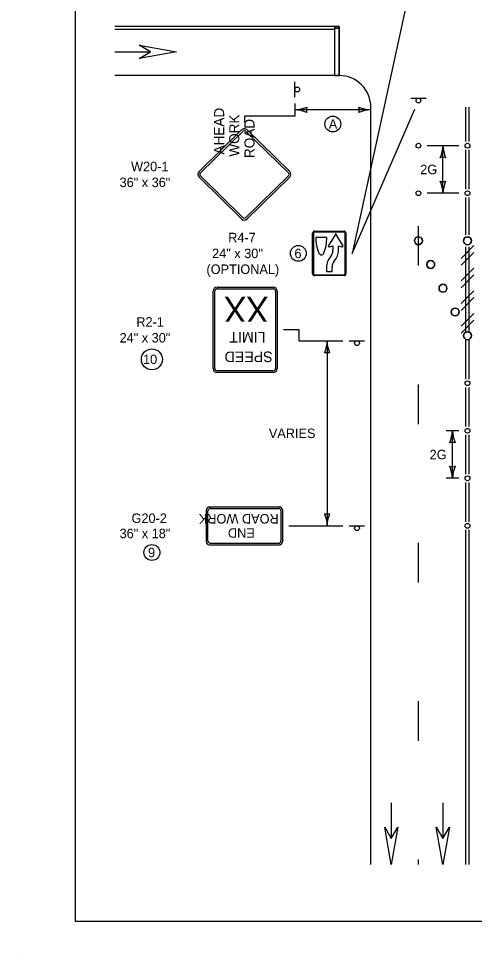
# Model space of a CAD drawing. Extents: x 49991.4 to 50021, y 49987.6 to 50011.4.
# Drawn here: x 49999.02 to 50001.9, y 49987.6 to 49993.5 of the extents above; entities that cross this region are included whole.
import ezdxf

# ---------------------------------------------------------------- set-up
doc = ezdxf.new("R2010")
doc.units = 0
for name, color, linetype in [('Level 1', 7, 'Continuous'), ('Level 2', 7, 'Continuous'), ('Level 25', 7, 'Continuous'), ('Level 3', 7, 'Continuous')]:
    doc.layers.add(name, color=color, linetype=linetype)

# ---------------------------------------------------------------- blocks, each defined once
blk = doc.blocks.new('R4.7')
at = {"layer": 'Level 25'}
for p, q in [((-42.9, -53.4), (-42.9, 48.9)), ((-40.7, 48.9), (-40.7, -53.4)), ((-37.6, 54.2), (36.5, 54.2)), ((36.5, 52), (-37.6, 52)), ((15.6, 47.6), (-3, 18.2)), ((34.1, 18.2), (15.6, 47.6)), ((39.5, -53.4), (39.5, 48.9)), ((41.7, 48.9), (41.7, -53.4)), ((-6.8, 38.4), (-35, 38.4)), ((0.3, 14.1), (8.5, 16.7)), ((8.5, 16.7), (8.5, 5.4)), ((22.6, 5.4), (22.6, 16.7)), ((22.6, 16.7), (30.9, 14.1)), ((-7.6, -36.9), (-7.6, -48.1)), ((6.5, -48.1), (6.5, -36.9)), ((-37.6, -56.5), (36.5, -56.5)), ((36.5, -58.7), (-37.6, -58.7)), ((-7.6, -48.1), (6.5, -48.1))]:
    blk.add_line(p, q, dxfattribs=at)
blk.add_lwpolyline([(15.8, 47.3), (15.5, 47.6)], dxfattribs=at)
for centre, radius, start, end in [((-37.6, 48.9), 5.29, 90, 180), ((-37.6, 48.9), 3.09, 90, 180), ((36.5, 48.9), 5.29, 0, 90), ((36.5, 48.9), 3.09, 0, 90), ((70.9, 38), 105.8, 179.7952, 201.7879), ((-112.6, 38), 105.8, 338.2124, 0.205), ((-0.6, 16.8), 2.79, 147.757, 287.6186), ((-16.2, 5.4), 24.7, 318.1901, 0), ((-16.2, 5.4), 38.8, 318.1901, 0), ((31.8, 16.8), 2.79, 252.3804, 32.2438), ((-20.9, 1.3), 7.06, 201.7877, 338.2132), ((31.2, -36.9), 38.8, 138.1903, 180), ((31.2, -36.9), 24.7, 138.1903, 180), ((-37.6, -53.4), 5.29, 180, 270), ((-37.6, -53.4), 3.09, 180, 270), ((36.5, -53.4), 3.09, 270, 0), ((36.5, -53.4), 5.29, 270, 0)]:
    blk.add_arc(centre, radius, start, end, dxfattribs=at)
blk = doc.blocks.new('ARR')
at = {"layer": 'Level 3'}
for centre, radius, start, end in [((1.53, 37.02), 37.05, 247.45601, 267.63952), ((-21.37, 0), 9.13, 342.13882, 17.86118), ((1.92, -38.79), 38.83, 92.82731, 112.07716)]:
    blk.add_arc(centre, radius, start, end, dxfattribs=at)
blk = doc.blocks.new('G20-2')
at = {"layer": 'Level 1'}
for p, q in [((0.2197, 0.1196), (-0.2203, 0.1196)), ((-0.2403, -0.1004), (-0.2403, 0.0996)), ((-0.2303, -0.0954), (-0.2303, 0.0946)), ((0.2147, 0.1096), (-0.2153, 0.1096)), ((0.2297, 0.0946), (0.2297, -0.0954)), ((0.2397, 0.0996), (0.2397, -0.1004)), ((0.2147, -0.1104), (-0.2153, -0.1104)), ((0.2196, -0.1204), (-0.2204, -0.1204))]:
    blk.add_line(p, q, dxfattribs=at)
for centre, radius, start, end in [((-0.2203, 0.0996), 0.02, 90, 180), ((0.2197, 0.0996), 0.02, 360, 90), ((-0.2153, 0.0946), 0.015, 90, 180), ((0.2147, 0.0946), 0.015, 360, 90), ((-0.2204, -0.1004), 0.02, 180, 270), ((-0.2153, -0.0954), 0.015, 180, 270), ((0.2147, -0.0954), 0.015, 270, 360), ((0.2196, -0.1004), 0.02, 270, 360)]:
    blk.add_arc(centre, radius, start, end, dxfattribs=at)
for s, p in [('END', (-0.0655, 0.015)), ('ROAD WORK', (-0.2162, -0.075))]:
    blk.add_text(s, height=0.06, rotation=360, dxfattribs=at).set_placement(p)

msp = doc.modelspace()

# ---------------------------------------------------------------- linework, layer by layer
at = {"layer": 'Level 1'}
for p, q in [((50001.0473, 49993.4505), (49999.6305, 49993.4505)), ((50001.0173, 49993.4305), (49999.6305, 49993.4305)), ((50001.0173, 49993.4505), (50001.0173, 49993.1404)), ((50001.0173, 49993.4405), (50001.0473, 49993.4405)), ((50001.0473, 49993.4505), (50001.0473, 49993.1404)), ((49999.6305, 49993.2905), (49999.8564, 49993.2905)), ((49999.6305, 49993.2901), (49999.8564, 49993.2901)), ((50001.0473, 49993.1404), (49999.6305, 49993.1404)), ((50000.7673, 49993.0044), (50000.7673, 49993.1004)), ((50001.4994, 49992.9977), (50001.5954, 49992.9977)), ((50001.2473, 49988.1586), (50001.2473, 49992.9404)), ((50001.8473, 49992.7239), (50001.8473, 49992.9404)), ((50001.8673, 49992.7239), (50001.8673, 49992.9404)), ((50000.163, 49992.5343), (50000.4313, 49992.7971)), ((50000.1716, 49992.5255), (50000.4399, 49992.7883)), ((50000.4586, 49992.7883), (50000.7268, 49992.5255)), ((50000.4672, 49992.7971), (50000.7354, 49992.5343)), ((50001.8473, 49992.4239), (50001.8473, 49992.6715)), ((50001.8673, 49992.4239), (50001.8673, 49992.6715)), ((50000.4313, 49992.2355), (50000.163, 49992.4983)), ((50000.4399, 49992.2443), (50000.1716, 49992.5071)), ((50000.7268, 49992.5071), (50000.4586, 49992.2443)), ((50000.7354, 49992.4983), (50000.4672, 49992.2355)), ((50001.8473, 49992.1356), (50001.8473, 49992.3715)), ((50001.8673, 49992.1356), (50001.8673, 49992.3715)), ((50001.5474, 49991.9404), (50001.5474, 49992.1904)), ((50001.5225, 49992.0977), (50001.5225, 49992.0977)), ((50001.8169, 49991.9865), (50001.8977, 49992.0673)), ((50001.8323, 49992.0977), (50001.8323, 49992.0977)), ((50001.8473, 49991.5239), (50001.8473, 49992.0598)), ((50001.8673, 49991.5239), (50001.8673, 49992.0598)), ((50001.8169, 49991.9436), (50001.8977, 49992.0244)), ((50001.5999, 49991.9477), (50001.5999, 49991.9477)), ((50001.8169, 49991.8436), (50001.8977, 49991.9244)), ((50001.8169, 49991.8008), (50001.8977, 49991.8816)), ((50000.2769, 49991.805), (50000.6313, 49991.805)), ((50000.2516, 49991.2902), (50000.2516, 49991.7797)), ((50000.2621, 49991.2902), (50000.2621, 49991.7797)), ((50000.2769, 49991.7944), (50000.6313, 49991.7944)), ((50000.6461, 49991.7797), (50000.6461, 49991.2902)), ((50000.6567, 49991.7797), (50000.6567, 49991.2902)), ((50001.6774, 49991.7977), (50001.6774, 49991.7977)), ((50001.8169, 49991.7008), (50001.8977, 49991.7816)), ((50001.8169, 49991.6579), (50001.8977, 49991.7387)), ((50001.7549, 49991.6477), (50001.7549, 49991.6477)), ((50001.8169, 49991.5579), (50001.8977, 49991.6387)), ((50001.8169, 49991.5151), (50001.8977, 49991.5959)), ((50001.1113, 49991.4657), (50001.2073, 49991.4657)), ((50001.8323, 49991.4977), (50001.8323, 49991.4977)), ((50001.8473, 49991.2239), (50001.8473, 49991.4748)), ((50001.8673, 49991.2239), (50001.8673, 49991.4715)), ((50000.6313, 49991.2755), (50000.2769, 49991.2755)), ((50000.6313, 49991.2649), (50000.2769, 49991.2649)), ((50000.4541, 49991.2649), (50000.4541, 49991.2649)), ((50001.5474, 49990.9404), (50001.5474, 49991.1904)), ((50001.8473, 49990.9239), (50001.8473, 49991.1715)), ((50001.8673, 49990.9239), (50001.8673, 49991.1715)), ((50001.8473, 49990.6239), (50001.8473, 49990.8715)), ((50001.8673, 49990.6239), (50001.8673, 49990.8715)), ((50001.8473, 49990.3239), (50001.8473, 49990.5715)), ((50001.8673, 49990.3239), (50001.8673, 49990.5715)), ((50001.1113, 49990.2977), (50001.2073, 49990.2977)), ((50001.8473, 49988.1586), (50001.8473, 49990.2715)), ((50001.8673, 49988.1586), (50001.8673, 49990.2715)), ((50001.5474, 49989.9404), (50001.5474, 49990.1904)), ((50001.5474, 49988.9404), (50001.5474, 49989.1904)), ((50001.376, 49988.5487), (50001.376, 49988.3228)), ((50001.3764, 49988.5487), (50001.3764, 49988.3228)), ((50001.7008, 49988.5487), (50001.7008, 49988.3228)), ((50001.7012, 49988.5487), (50001.7012, 49988.3228)), ((50001.5474, 49988.1586), (50001.5474, 49988.1904)), ((49999.0245, 49987.5988), (49999.0245, 49987.5988))]:
    msp.add_line(p, q, dxfattribs=at)
for points in [[(49999.3835, 49998.9992), (50016.7501, 49998.9992), (50016.7501, 49987.7988), (49999.3835, 49987.7988)], [(49999.7841, 49993.3321), (50000.0206, 49993.2905), (49999.7841, 49993.2485), (49999.8563, 49993.2905)], [(50001.418, 49988.3951), (50001.3764, 49988.1586), (50001.3344, 49988.3951), (50001.3764, 49988.3229)], [(50001.7428, 49988.3951), (50001.7012, 49988.1586), (50001.6592, 49988.3951), (50001.7012, 49988.3229)]]:
    msp.add_lwpolyline(points, close=True, dxfattribs=at)
for points in [[(50001.0473, 49993.4405), (50001.0473, 49993.4505), (50001.0173, 49993.4505), (50001.0173, 49993.4405), (50001.0473, 49993.4405)], [(50001.0173, 49993.1404), (50001.0473, 49993.1404), (50001.0473, 49993.4405), (50001.0173, 49993.4405), (50001.0173, 49993.1404)]]:
    msp.add_lwpolyline(points, dxfattribs=at)
for centre, radius in [((50000.7825, 49993.0525), 0.0152), ((50001.5475, 49992.9825), 0.0152), ((50001.5474, 49992.6977), 0.015), ((50001.8573, 49992.6977), 0.015), ((50001.5474, 49992.3977), 0.015), ((50001.8573, 49992.3977), 0.015), ((50001.5474, 49992.0977), 0.025), ((50001.8573, 49992.0977), 0.025), ((50001.6249, 49991.9477), 0.025), ((50001.7024, 49991.7977), 0.025), ((50001.7798, 49991.6477), 0.025), ((50001.8573, 49991.4977), 0.025), ((50001.1594, 49991.4506), 0.0152), ((50001.8573, 49991.1977), 0.015), ((50001.8573, 49990.8977), 0.015), ((50001.8573, 49990.5977), 0.015), ((50001.1594, 49990.2825), 0.0152), ((50001.8573, 49990.2977), 0.015)]:
    msp.add_circle(centre, radius, dxfattribs=at)
for centre, radius, start, end in [((50001.0473, 49992.9404), 0.2, 359.99985, 90), ((50001.5474, 49992.0977), 0.025, 0, 180), ((50001.8573, 49992.0977), 0.025, 0, 180), ((50001.5474, 49992.0977), 0.025, 180, 0), ((50001.8573, 49992.0977), 0.025, 180, 0), ((50001.6249, 49991.9477), 0.025, 0, 180), ((50001.6249, 49991.9477), 0.025, 180, 0), ((50000.2769, 49991.7797), 0.0253, 90, 180), ((50000.6313, 49991.7797), 0.0253, 360, 90), ((50001.7024, 49991.7977), 0.025, 0, 180), ((50000.2769, 49991.7797), 0.0148, 90, 180), ((50000.6313, 49991.7797), 0.0148, 360, 90), ((50001.7024, 49991.7977), 0.025, 180, 0), ((50001.7798, 49991.6477), 0.025, 0, 180), ((50001.7798, 49991.6477), 0.025, 180, 0), ((50001.8573, 49991.4977), 0.025, 0, 180), ((50001.8573, 49991.4977), 0.025, 180, 0), ((50000.2769, 49991.2902), 0.0253, 180, 270), ((50000.2769, 49991.2902), 0.0148, 180, 270), ((50000.6313, 49991.2902), 0.0148, 270, 360), ((50000.6313, 49991.2902), 0.0253, 270, 360)]:
    msp.add_arc(centre, radius, start, end, dxfattribs=at)
for centre, major_axis, ratio, start_param, end_param in [((50000.4492, 49992.7792), (0.0255, 0), 0.98963, 0.785394, 2.356194), ((50000.4492, 49992.7792), (0.0132, 0), 0.98, 0.785394, 2.356194), ((50000.181, 49992.5163), (-0.0255, 0), 0.98963, 5.497795, 7.068583), ((50000.181, 49992.5163), (-0.0132, 0), 0.98, 5.497795, 7.068583), ((50000.7174, 49992.5163), (0.0132, 0), 0.98, 5.497787, 7.068583), ((50000.7174, 49992.5163), (0.0255, 0), 0.98963, 5.497787, 7.068583), ((50000.4492, 49992.2535), (0.0255, 0), 0.98963, 3.926991, 5.497787), ((50000.4492, 49992.2535), (0.0132, 0), 0.98, 3.926991, 5.497787)]:
    msp.add_ellipse(centre, major_axis=major_axis, ratio=ratio, start_param=start_param, end_param=end_param, dxfattribs=at)
at = {"layer": 'Level 2'}
for centre, radius in [((50001.0073, 49992.8343), 0.0501), ((50000.7894, 49992.0177), 0.0501), ((49999.8653, 49991.3488), 0.0662), ((49999.8653, 49990.1296), 0.0501)]:
    msp.add_circle(centre, radius, dxfattribs=at)
at = {"layer": 'Level 3'}
for p, q in [((50001.5475, 49993.945), (50001.1302, 49992.0177)), ((50000.7673, 49992.9644), (50000.7673, 49992.8844)), ((50001.2473, 49992.9244), (50000.7673, 49992.9244)), ((50001.1302, 49992.0177), (50001.5249, 49992.9273)), ((50000.4492, 49992.8844), (50000.4492, 49992.8444)), ((50000.7673, 49992.8844), (50000.4492, 49992.8844)), ((50001.8023, 49992.6977), (50001.6024, 49992.6977)), ((50001.7024, 49992.3977), (50001.7024, 49992.6977)), ((50001.8023, 49992.3977), (50001.6024, 49992.3977)), ((50000.7943, 49991.4657), (50001.0713, 49991.4657)), ((50000.9713, 49991.4657), (50000.9713, 49990.2977)), ((50001.8023, 49990.898), (50001.7222, 49990.898)), ((50001.7622, 49990.5977), (50001.7622, 49990.898)), ((50001.8023, 49990.5977), (50001.7222, 49990.5977)), ((50000.7297, 49990.2977), (50001.0713, 49990.2977))]:
    msp.add_line(p, q, dxfattribs=at)
msp.add_lwpolyline([(50000.7943, 49991.4657), (50000.7943, 49991.535), (50000.6967, 49991.535)], dxfattribs=at)
for centre, radius, start, end in [((50001.48, 49992.7069), 0.2225, 337.45601, 357.63952), ((50001.9353, 49992.7092), 0.2332, 182.82731, 202.07716), ((50001.7024, 49992.5694), 0.0548, 72.13882, 107.86118), ((50001.7024, 49992.526), 0.0548, 252.13882, 287.86118), ((50001.4694, 49992.3862), 0.2332, 2.82731, 22.07716), ((50001.9247, 49992.3885), 0.2225, 157.45601, 177.63952), ((50001.5399, 49990.9072), 0.2225, 337.45601, 357.63952), ((50001.9952, 49990.9095), 0.2332, 182.82731, 202.07716), ((50001.7622, 49990.7697), 0.0548, 72.13882, 107.86118), ((50001.7622, 49990.726), 0.0548, 252.13882, 287.86118), ((50001.5293, 49990.5862), 0.2332, 2.82731, 22.07716), ((50001.9846, 49990.5885), 0.2225, 157.45601, 177.63952)]:
    msp.add_arc(centre, radius, start, end, dxfattribs=at)

# ---------------------------------------------------------------- block references
at = {"layer": 'Level 1', "xscale": 0.002488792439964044, "yscale": 0.002488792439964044}
msp.add_blockref('R4.7', (50000.9863, 49992.0232), dxfattribs=at)
at = {"layer": 'Level 2'}
for p, xscale, yscale, rotation in [((50000.7673, 49992.9244), 0.005999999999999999, 0.006, -179.99999999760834), ((50001.2473, 49992.9244), 0.005999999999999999, 0.006, 2.3916545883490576e-09), ((50000.9713, 49991.4657), 0.006, -0.006, 90), ((50000.9713, 49990.2977), 0.006, -0.006, -90)]:
    msp.add_blockref('ARR', p, dxfattribs=dict(at, xscale=xscale, yscale=yscale, rotation=rotation))
at = {"layer": 'Level 3', "xscale": 1.001, "yscale": 1.001, "rotation": 179.99999999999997}
msp.add_blockref('G20-2', (50000.4491, 49990.2973), dxfattribs=at)

# ---------------------------------------------------------------- texts
at = {"layer": 'Level 1'}
for s, height, rotation, p in [('AHEAD', 0.06395, 90, (50000.3214, 49992.6422)), ('WORK', 0.06395, 90, (50000.4173, 49992.6285)), ('ROAD', 0.06395, 90, (50000.5131, 49992.6196)), ('XX', 0.15772, 180, (50000.6012, 49991.7439)), ('LIMIT', 0.06695, 180, (50000.5829, 49991.5219)), ('SPEED', 0.06695, 180, (50000.6272, 49991.3982))]:
    msp.add_text(s, height=height, rotation=rotation, dxfattribs=at).set_placement(p)
at = {"layer": 'Level 2'}
for s, rotation, p in [('A', 0, (50000.9816, 49992.8043)), ('W20-1', 360, (49999.7337, 49992.5363)), ('36" x 36"', 360, (49999.6614, 49992.4363)), ('VARIES', 360, (50000.6033, 49990.8517))]:
    msp.add_text(s, height=0.06, rotation=rotation, dxfattribs=at).set_placement(p)
for s, height, p in [('2G', 0.06006, (50001.5586, 49992.5177)), ('R4-7', 0.06, (50000.3468, 49992.0877)), ('24" x 30"', 0.06, (50000.2453, 49991.9877)), ('6', 0.06, (50000.7649, 49991.9877)), ('(OPTIONAL)', 0.06, (50000.2095, 49991.8877)), ('R2-1', 0.06, (49999.767, 49991.555)), ('24" x 30"', 0.06, (49999.6614, 49991.455)), ('10', 0.06006, (49999.8092, 49991.3189)), ('2G', 0.06006, (50001.6185, 49990.7178)), ('G20-2', 0.06, (49999.7367, 49990.3157)), ('36" x 18"', 0.06, (49999.6614, 49990.2197)), ('9', 0.06, (49999.8408, 49990.0996))]:
    msp.add_text(s, height=height, dxfattribs=at).set_placement(p)

doc.saveas('drawing.dxf')
